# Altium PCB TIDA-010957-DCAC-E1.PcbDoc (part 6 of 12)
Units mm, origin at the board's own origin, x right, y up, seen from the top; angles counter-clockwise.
Board outline 300 x 300 mm, 4 copper layers (Top Layer, Layer 1, Layer 2, Bottom Layer), stack 1.787 mm thick; 1159 components, 619 nets, 3431 pads, 2942 vias.
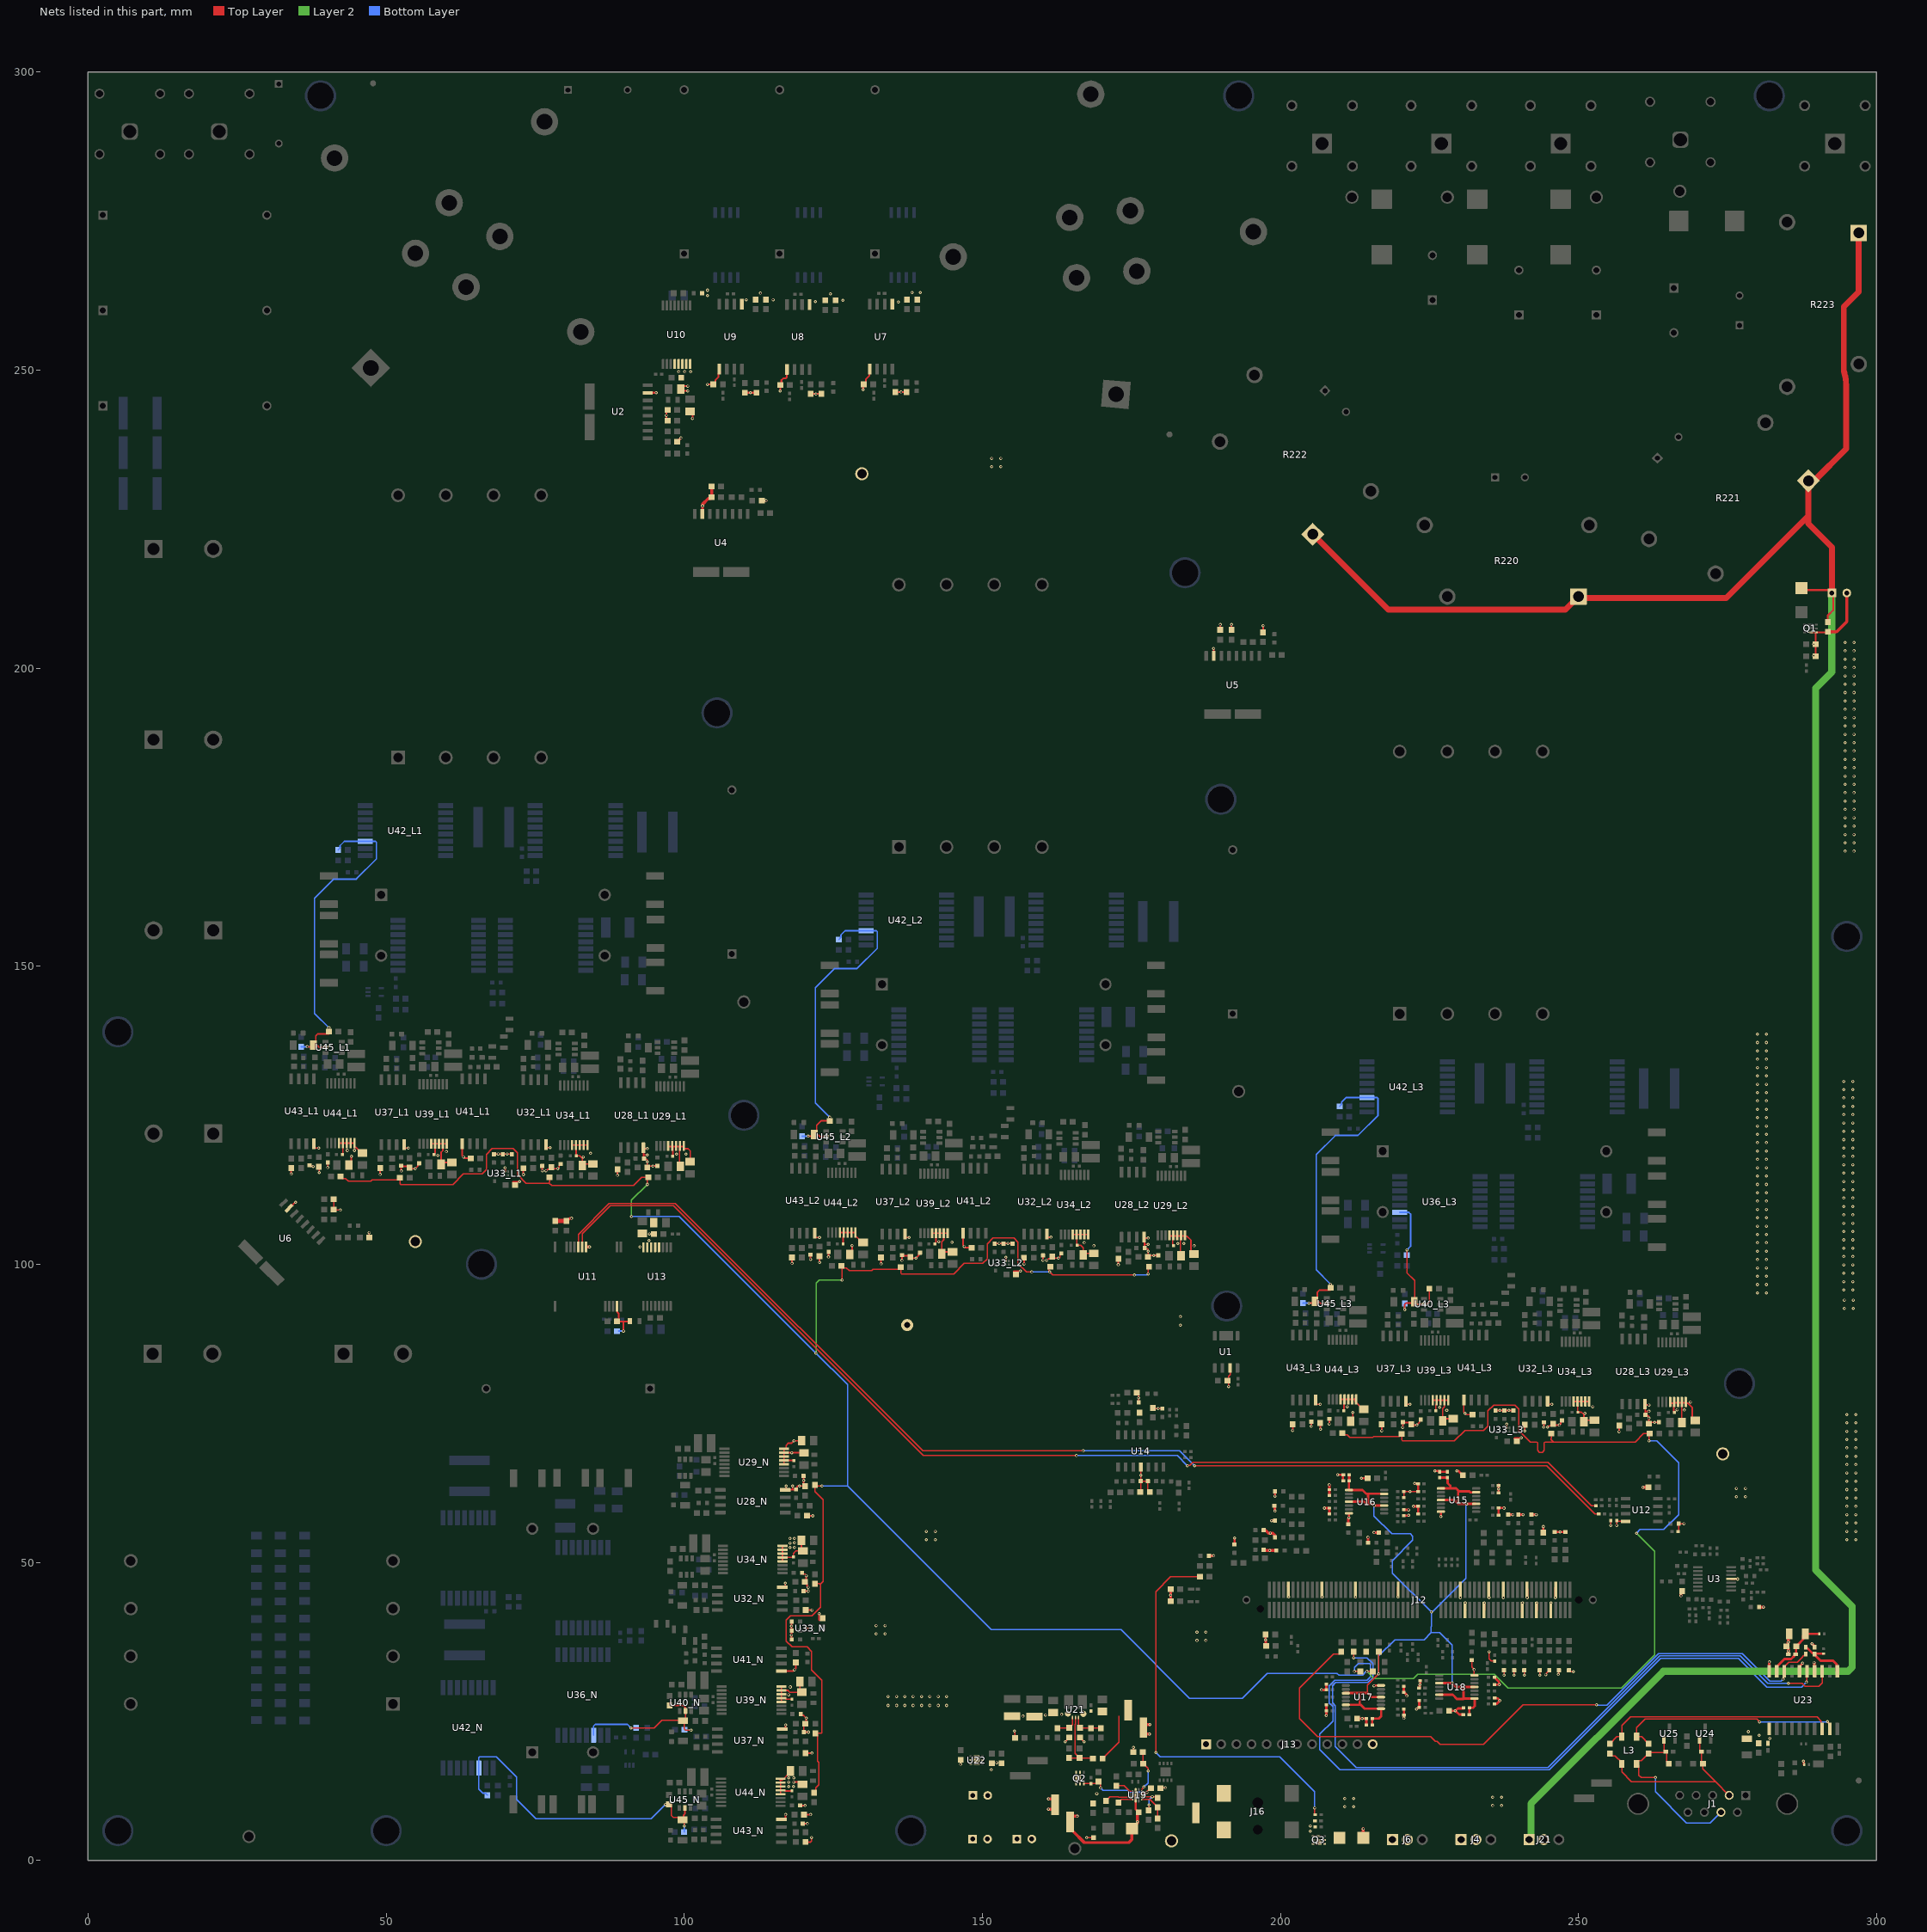
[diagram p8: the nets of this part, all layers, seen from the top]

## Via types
v1: diameter 0.508, hole 0.254, Top Layer to Bottom Layer, tented both sides, 2942 vias

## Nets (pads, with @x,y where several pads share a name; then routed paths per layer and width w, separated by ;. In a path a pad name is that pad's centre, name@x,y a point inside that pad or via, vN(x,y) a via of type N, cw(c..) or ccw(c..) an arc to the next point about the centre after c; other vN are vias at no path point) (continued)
10V_S3_GaN_L3: C229_L3.1 C232_L3.1 R306_L3.2 R310_L3.2 U36_L3.11 U40_L3.5 | length 27.2
  Top Layer w0.254: v1(220.842,92.373) 220.842,93.303 221.047,93.508 C232_L3.1@222.429,93.508 ; v1(221.222,102.422) 221.222,98.546 222.51,97.257 222.51,93.427 222.654,93.283 U40_L3.5@224.083,93.283 224.103,93.303 224.61,93.303 224.983,93.676 R310_L3.2@224.983,95.942
  Bottom Layer w0.254: U36_L3.11@220,108.7 221.544,108.7 221.824,108.42 221.824,103.025 v1(221.222,102.422) C229_L3.1@221.222,101.55 ; v1(220.842,92.373) 220.842,93.378 R306_L3.2@220.897,93.433
10V_S3_GaN_N: C229_N.1 C232_N.1 R306_N.2 R310_N.2 U36_N.11 U40_N.5 | length 27.2
  Top Layer w0.254: v1(91.078,22.222) 94.954,22.222 96.243,23.51 100.073,23.51 100.217,23.654 U40_N.5@100.217,25.083 100.197,25.103 100.197,25.61 99.824,25.983 R310_N.2@97.558,25.983 ; C232_N.1@99.992,23.429 99.992,22.047 100.197,21.842 v1(101.127,21.842)
  Bottom Layer w0.254: U36_N.11@84.8,21 84.8,22.544 85.08,22.824 90.475,22.824 v1(91.078,22.222) C229_N.1@91.95,22.222 ; R306_N.2@100.067,21.897 100.122,21.842 v1(101.127,21.842)
10V_S4_GaN_L1: C247_L1.1 C249_L1.1 R323_L1.2 R327_L1.2 U42_L1.11 U45_L1.5 | length 55.3
  Top Layer w0.254: v1(36.786,136.484) 37.513,136.484 C249_L1.1@37.811,136.783 ; U45_L1.5@39.402,136.383 38.801,136.383 38.551,136.633 37.961,136.633 C249_L1.1@37.811,136.783 ; U45_L1.5@39.479,136.383 U45_L1.5@39.801,136.383 ; v1(40.403,139.667) 40.403,138.659 38.535,138.659 38.21,138.334 38.21,137.181 C249_L1.1@37.811,136.783
  Bottom Layer w0.254: R323_L1.2@35.768,136.509 35.793,136.484 v1(36.786,136.484) ; v1(40.403,139.667) 38,142.07 38,161.388 41.231,164.619 44.245,164.619 45.003,164.619 48.375,167.991 48.375,170.801 48.226,170.95 U42_L1.11@46.5,170.95 43,170.95 42.275,170.225 42.275,169.825 C247_L1.1@41.95,169.5
10V_S4_GaN_L2: C247_L2.1 C249_L2.1 R323_L2.2 R327_L2.2 U42_L2.11 U45_L2.5 | length 55.1
  Top Layer w0.254: v1(120.786,121.484) 121.513,121.484 C249_L2.1@121.811,121.783 ; U45_L2.5@123.402,121.383 122.801,121.383 122.551,121.633 121.961,121.633 C249_L2.1@121.811,121.783 ; U45_L2.5@123.479,121.383 U45_L2.5@123.801,121.384 ; v1(124.403,124.667) R327_L2.2@124.403,124.134 ; C249_L2.1@121.811,121.783 122.21,122.181 122.21,123.334 122.935,124.059 R327_L2.2@124.328,124.059 ; R327_L2.2@124.328,124.059 R327_L2.2@124.403,124.059 R327_L2.2@124.403,124.134 ; R327_L2.2@124.328,124.059 R327_L2.2@124.403,124.134
  Bottom Layer w0.254: R323_L2.2@119.768,121.509 119.793,121.484 v1(120.786,121.484) ; v1(124.403,124.667) 122,127.07 122,146.388 125.231,149.619 128.245,149.619 129.003,149.619 132.375,152.991 132.375,155.801 132.226,155.95 U42_L2.11@130.5,155.95 127,155.95 126.275,155.225 126.275,154.825 C247_L2.1@125.95,154.5
10V_S4_GaN_L3: C247_L3.1 C249_L3.1 R323_L3.2 R327_L3.2 U42_L3.11 U45_L3.5 | length 55.3
  Top Layer w0.254: v1(204.786,93.484) 205.513,93.484 C249_L3.1@205.811,93.783 ; U45_L3.5@207.801,93.384 207.401,93.384 207.402,93.383 206.801,93.383 206.551,93.633 205.961,93.633 C249_L3.1@205.811,93.783 ; v1(208.403,96.667) R327_L3.2@208.403,96.059 208.403,95.659 206.535,95.659 206.21,95.334 206.21,94.181 C249_L3.1@205.811,93.783
  Bottom Layer w0.254: R323_L3.2@203.768,93.509 203.793,93.484 v1(204.786,93.484) ; v1(208.403,96.667) 206,99.07 206,118.388 209.231,121.619 212.245,121.619 213.003,121.619 216.375,124.991 216.375,127.801 216.226,127.95 U42_L3.11@214.5,127.95 211,127.95 210.275,127.225 210.275,126.825 C247_L3.1@209.95,126.5
10V_S4_GaN_N: C247_N.1 C249_N.1 R323_N.2 R327_N.2 U42_N.11 U45_N.5 | length 55.3
  Top Layer w0.254: v1(96.833,9.403) 97.841,9.403 97.841,7.535 98.166,7.21 99.319,7.21 C249_N.1@99.717,6.811 ; v1(100.016,5.786) 100.016,6.513 C249_N.1@99.717,6.811 ; U45_N.5@100.1,8.783 100.1,7.783 99.91,7.594 99.91,7.004 C249_N.1@99.717,6.811
  Bottom Layer w0.254: C247_N.1@67,10.95 66.675,11.275 66.275,11.275 65.55,12 U42_N.11@65.55,15.5 65.55,17.226 65.699,17.375 68.509,17.375 71.881,14.003 71.881,13.245 71.881,10.231 75.112,7 94.43,7 v1(96.833,9.403) ; R323_N.2@99.991,4.768 100.016,4.793 v1(100.016,5.786)
12V: C4.1 C26.1 C27.1 C259.1 C260.1 D3.1 D17.1 J4.1 J6.1 J15.2 J21.1 R220.1 R221.1 R222.1 R223.1 | length 429.7
  Top Layer w0.2: J15.2@161.674,8.6 162.209,9.135 J15.2@162.209,9.358 162.209,9.765 J15.2@161.674,10.3
  Top Layer w0.3: D3.1@287.3,213.1 292,213.1 C26.1@292.5,212.6 ; C27.1@292,207.5 C27.1@291.8,207.7 291.8,208.8 292.7,209.7 C26.1@292.7,212.5
  Top Layer w0.5: v1(161.102,8.611) v1(161.102,8.611) 161.664,8.609 J15.2@161.674,8.6 ; v1(161.113,10.308) 161.115,10.306 161.667,10.306 J15.2@161.674,10.3 ; D17.1@213.9,3.8 v1(213.9,5.286) v1@213.9,5.312
  Top Layer w1: R222.1@205.668,222.2 218.068,209.8 247.8,209.8 R220.1@250,212 ; R220.1@250.214,211.786 274.786,211.786 288.551,225.551 ; C26.1@292.5,212.6 292.5,220.3 288.551,224.249 288.551,225.551 ; R223.1@297,273 297,263.1 294.492,260.592 294.492,249.922 cw(c284.326,247.007) 294.902,247.007 294.902,236.802 289.519,231.419 R221.1@288.551,231.419 288.551,225.551
  Layer 2 w1.2: J21.1@241.7,3.5 242.025,3.825 242.025,9.525 264.218,31.718 295.197,31.718 295.9,32.42 295.9,42.6 289.777,48.723 289.777,48.8 289.777,196.641 292.5,199.364 C26.1@292.5,212.6
12V_FET_DRAIN: Q2.1 Q2.2 Q2.5 Q2.6 Q2.8 R210.1
+5VISO_DC-: C87.2 C88.1 L8.2 U11.5 | length 7.2
  Top Layer w0.3: C88.1@88.729,90.418 89,90.689 89,91.717 88.804,91.913 88.804,92.879 U11.5@88.729,92.954 ; C88.1@88.8,90.4 89.8,90.4 ; v1(89.8,88.8) 89.8,90.4 ; L8.2@90.853,90.4 89.8,90.4
  Bottom Layer w0.3: C87.2@89,88.8 v1(89.8,88.8)
+5VISO_PCC: C54.1 C55.2 C61.1 C62.2 C68.1 C69.2 FB10.1 U7.1 U8.1 U9.1
  other v1: 135.9,261.4 122,261.5 126.6,261.7 110.4,261.8 114.9,261.8 103.9,262.5 124.5,262.8 112.8,262.9 138.2,263 139.6,263 103.9,263.4
+12V_OUT: C133.1 D4.2 D5.1 J15.1 J17.1 R205.2 R209.2 TP5.1 U19.6 | length 28.4
  Top Layer w0.2: J15.1@164.749,6.437 164.749,6.865 J15.1@165.284,7.4 ; v1(167.5,3.8) 167.504,3.796 D4.2@168.682,3.796 ; D5.1@175.1,5.321 D5.1@175.119,5.34 ; v1(175.334,18.976) 175.334,18.18 R205.2@175.339,18.175 ; C133.1@175.841,8.469 C133.1@176.216,8.094 ; J17.1@177.527,22.8 J17.1@177.021,22.294 177.021,21.735 J17.1@177.556,21.2 ; R209.2@179.879,12.125 179.913,12.16 v1(180.72,12.16)
  Top Layer w0.3: U19.6@175.729,10.925 175.729,8.581 C133.1@175.841,8.469
  Top Layer w0.5: J15.1@164.749,6.437 165.134,6.052 165.134,4.964 167.102,2.995 174.595,2.995 175.1,3.5 D5.1@175.1,5.321 ; J15.1@165.284,7.4 v1(165.9,7.4) ; D5.1@175.119,5.34 176.027,6.248 176.027,7.894 C133.1@176.227,8.094 ; J17.1@177.527,22.8 v1(178.1,22.8) ; J17.1@177.556,21.2 v1(178,21.2)
  other v1: 176,6.5 169.2,11.2
AUX_IN_PWR: J14.1 J16.1 J16.1A
BUFF_EN: C108.1 C115.1 C120.1 C126.1 R65.1 R169.2 R184.2 R189.2 R199.2 U15.1 U15.4 U15.10 U15.13 U16.1 U16.4 U16.10 U16.13 U17.1 U17.4 U17.10 U17.13 U18.1 U18.4 U18.10 U18.13 | length 151.5
  Top Layer w0.2: 214.623,28.077 214.623,29.424 216.499,31.3 R65.1@216.5,35
  Top Layer w0.4: U17.10@210.8,28.077 213.3,28.077 ; U17.13@210.966,26.102 213.3,26.102 ; U16.4@211.498,60.175 214.025,60.175 214.4,59.8 214.7,59.8 ; C115.1@211.5,63.6 211.5,62.127 U16.1@211.498,62.125 213.775,62.125 214.4,61.5 214.7,61.5 ; R184.2@211.5,64.7 211.506,64.7 211.548,64.658 C115.1@211.548,63.675 ; 213.3,28.1 213.3,28.077 ; C120.1@215.4,22.7 R189.2@215.4,23.8 216.5,23.8 216.9,24.2 U17.1@216.9,25.4 ; U16.10@216.8,59.55 v1(215.725,59.55) 215.475,59.8 214.7,59.8 ; U17.1@216.866,25.452 214.148,25.452 213.498,26.102 213.3,26.102 ; U17.4@216.866,27.402 215.298,27.402 214.623,28.077 213.3,28.077 ; U16.13@217.3,61.5 214.7,61.5 ; U18.13@226.65,27.8 228.9,27.8 229.6,27.1 230.7,27.1 230.7,29.1 ; U18.10@226.65,29.75 226.658,29.758 228.766,29.758 v1(228.773,29.765) 229.438,29.1 230.7,29.1 ; C108.1@226.7,64.2 R169.2@228,64.2 228.05,64.15 228.05,63.3 228.5,62.85 228.5,62.442 ; U15.4@226.921,60.452 229.148,60.452 229.798,59.802 ; U15.1@226.921,62.402 228.065,62.402 ; 228.105,62.402 229.495,62.402 229.798,62.099 ; 229.798,62.102 229.798,59.802 ; 229.798,62.102 230,61.9 231.697,61.9 231.87,61.727 U15.13@232.2,61.727 ; 230.7,27.15 U18.1@232.55,27.15 ; R199.2@231.7,24.689 C126.1@231.7,25.6 232.3,25.6 232.6,25.9 U18.1@232.6,27.1 ; U18.4@232.6,29.1 U18.4@232.55,29.1 230.7,29.1 ; U15.10@232.698,59.802 229.798,59.802 ; 213.3,26.102 213.3,28.077 ; 214.7,59.8 214.7,61.5
  Bottom Layer w0.2: v1(215.725,59.55) 215.7,59.525 215.7,57.8 218.7,54.8 221.8,54.8 222.2,54.4 222.2,53.7 218.8,50.3 218.8,48.2 v1(225.31,41.69) ; v1(216.5,31.3) 216.5,34.3 219.2,37 224.1,37 225.3,38.2 ; v1(228.773,29.765) 228.773,36.127 226.7,38.2 225.3,38.2 ; v1(231.248,59.802) 231.1,59.654 231.1,47.3 225.628,41.828 225.558,41.828 225.42,41.69 v1(225.31,41.69) ; 225.3,38.2 225.3,39.24 225.31,39.249 v1(225.31,41.69)
CAN_EN: R88.1 R224.1 U23.8 | length 112.6
  Top Layer w0.2: R88.1@210.2,35 210.2,34.975 209.825,34.6 208.907,34.6 203.2,28.893 203.2,23.8 206.2,20.8 225.2,20.8 226,20 226.279,20 226.779,19.5 234.1,19.5 240.7,26.1 v1(253,26.1) ; v1(284.3,30.4) 284.378,30.478 284.378,31.608 U23.8@284.52,31.75 284.52,32.5 285.248,33.228 286.728,33.228 287.6,34.1 287.6,34.15 R224.1@288.1,34.65
  Bottom Layer w0.2: v1(253,26.1) 253.056,26.044 254.744,26.044 263.4,34.7 277.5,34.7 282.1,30.1 284,30.1 v1(284.3,30.4)
CAN_GND2: C153.2 C154.2 C155.2 FB18.1 U23.11 | length 0.8
  Top Layer w0.2: v1(287.725,16.675) v1@287.787,16.612 ; FB18.1@287.787,16.113 FB18.1@287.85,16.05
  Top Layer w0.4: FB18.1@287.787,16.113 v1@287.787,16.612
  Bottom Layer w0.2: v1(287.725,16.675) v1@287.725,16.775
  other v1: 282.1,20.5 280.3,21 278.5,21.6
CAN_RX: R71.1 U23.5 | length 121.2
  Top Layer w0.2: v1(212.4,31.7) R71.1@213.4,31.7 ; v1(288.2,29.9) 288.265,29.965 288.265,31.685 U23.5@288.33,31.75
  Bottom Layer w0.2: v1(212.4,31.7) 212.4,32.4 213.05,33.05 214.908,33.05 215.105,32.853 215.105,30.817 214.51,30.222 209.122,30.222 208.2,29.3 208.2,26.419 208.8,25.819 208.8,23.383 206.6,21.183 206.6,18.6 210,15.2 245.066,15.2 263.766,33.9 276.8,33.9 281.605,29.095 287.395,29.095 v1(288.2,29.9)
CAN_TX: R84.1 U23.3 | length 119.9
  Top Layer w0.2: v1(212.3,34) R84.1@212.3,35 ; v1(285.2,29.7) 287.5,29.7 288,29.2 290.3,29.2 290.87,29.77 U23.3@290.87,31.75
  Bottom Layer w0.2: v1(212.3,34) 214.524,34 215.505,33.019 215.505,30.651 214.675,29.822 209.288,29.822 208.733,29.267 208.733,26.451 209.2,25.984 209.2,19.099 212.699,15.6 244.9,15.6 263.6,34.3 277.1,34.3 281.7,29.7 v1(285.2,29.7)
CAN_VDD: C6.1 C147.1 C148.1 FB12.2 U23.9 | length 11.2
  Top Layer w0.2: C148.1@286.4,34.6 C148.1@286.5,34.7
  Top Layer w0.4: U23.9@283.25,31.75 283.25,32.5 284.55,33.8 285.666,33.8 286.2,34.334 286.2,34.5 C148.1@286.267,34.567 ; C148.1@286.5,34.7 C147.1@286.5,35.9 286.525,35.9 286.8,36.175 286.8,36.2 287.7,37.1 287.7,37.666 288.05,38.016 FB12.2@290.4,38.016
CAN_VIO: C152.1 FB13.2 R224.2 U23.1 | length 9.2
  Top Layer w0.2: C152.1@289.6,34.5 C152.1@289.6,34.6
  Top Layer w0.4: R224.2@288.1,35.734 288.266,35.734 289.2,34.8 289.5,34.8 289.6,34.7 C152.1@289.6,34.6 289.7,34.7 FB13.2@291.1,34.7 ; C152.1@289.6,34.5 290.6,33.5 292.7,33.5 293.31,32.89 293.31,31.85 U23.1@293.41,31.75
CANH: L3.1 R225.2 U23.19 | length 38.2
  Top Layer w0.2: R225.2@261.75,19.55 261.75,19.575 260.575,20.75 L3.1@259.75,20.75 259.75,22.25 261.2,23.7 279.899,23.7 280.347,23.252 v1(280.377,23.252) ; v1(291.746,23.3) 291.805,23.241 291.805,23.135 292.14,22.8 U23.19@292.14,22.05
  Bottom Layer w0.2: v1(280.377,23.252) 291.698,23.252 v1(291.746,23.3)
CANHI: C156.1 J1.7 L3.4 R225.1 R226.2 U25.1 | length 31.4
  Top Layer w0.2: v1(262.9,13.9) 260.5,13.9 260.1,14.3 260.1,15.85 L3.4@259.75,16.2 259.75,16.375 260.1,16.725 260.526,16.725 261.35,17.55 261.375,17.55 261.75,17.925 R225.1@261.75,17.95 261.9,18.1 264.4,18.1 C156.1@264.55,18.25 ; U25.1@264.3,20.2 264.37,20.13 264.37,18.43 C156.1@264.55,18.25 ; R226.2@265.15,16.25 264.808,16.592 264.808,18.092 C156.1@264.65,18.25 C156.1@264.55,18.25
  Bottom Layer w0.2: v1(262.9,13.9) 262.9,11.528 268.128,6.3 272.105,6.3 J1.7@273.885,8.08
CANL: L3.2 R228.2 U23.18 | length 40.2
  Top Layer w0.2: R228.2@255.25,19.55 255.25,19.575 256.425,20.75 L3.2@257.25,20.75 257.25,22.65 258.7,24.1 290,24.1 290.7,23.4 290.7,22.22 U23.18@290.87,22.05
CANLO: C158.2 J1.2 L3.3 R227.1 R228.1 U24.1 | length 32
  Top Layer w0.2: R228.1@255.25,17.95 255.25,17.925 255.625,17.55 256.125,17.55 257.25,16.425 L3.3@257.25,16.2 257.25,14.85 258.9,13.2 272.99,13.2 ; U24.1@270.3,20.2 270.369,20.131 270.369,18.45 270.569,18.25 C158.2@270.65,18.25 270.65,16.45 R227.1@270.85,16.25 270.85,15.34 272.99,13.2 ; J1.2@275.27,10.92 272.99,13.2
DC_VSEN+: R139.2 U11.11 | length 197
  Top Layer w0.2: U11.11@82.229,102.904 82.229,105.029 87.4,110.2 98.515,110.2 140.015,68.7 v1(166.9,68.7) ; v1(185.6,66.2) 244.681,66.2 252.4,58.481 252.741,58.14 R139.2@253.383,58.14
  Bottom Layer w0.2: v1(166.9,68.7) 183.1,68.7 v1(185.6,66.2)
DC_VSEN-: R141.2 U11.10 | length 195.5
  Top Layer w0.2: U11.10@82.879,102.904 82.879,105.114 87.566,109.8 98.2,109.8 140.1,67.9 v1(165.8,67.9) ; v1(184.4,66.2) 184.478,66.278 184.823,66.278 185.349,66.805 244.895,66.805 252.2,59.5 R141.2@252.85,59.5
  Bottom Layer w0.2: v1(165.8,67.9) 182.7,67.9 v1(184.4,66.2)
DCDC_EN: C146.1 R213.1 R216.1 U21.6 | length 11.3
  Top Layer w0.2: R216.1@164.538,17.171 C146.1@166.32,17.171 ; U21.6@165.633,24.004 165.633,22.874 165.545,22.786 165.545,17.971 166.32,17.196 C146.1@166.32,17.171 ; R213.1@168.571,17.096 168.496,17.171 C146.1@166.32,17.171
DCDC_FB: C137.2 R214.1 R215.2 U21.7 | length 5.4
  Top Layer w0.2: U21.7@166.133,24.004 166.133,22.475 R215.2@166.383,22.225 168.177,22.225 C137.2@168.207,22.196 R214.1@169.858,22.196
DCDC_PG: R218.1 R219.2 U21.5 | length 4
  Top Layer w0.2: R218.1@162.608,22.196 164.554,22.196 R219.2@164.583,22.225 164.583,22.25 165.133,22.8 U21.5@165.133,24.004
DCDC_VIN: C141.1 C142.2 J17.2 R213.2 U21.1 | length 8.2
  Top Layer w0.2: R213.2@170.171,17.096 170.196,17.096 170.571,17.471 170.571,17.496 172.9,19.825 172.9,24.2
EF_dVdt: C135.1 U19.7 | length 2.8
  Top Layer w0.2: C135.1@172.479,12.525 173.775,12.525 174.708,11.592 174.912,11.592 174.929,11.575
EF_EN: R204.1 R208.2 U19.1 | length 5.1
  Top Layer w0.2: U19.1@176.729,10.225 178.116,10.225 179.391,8.95 R208.2@179.391,8.925 R204.1@179.391,7.046
EF_ILIM: R206.2 U19.9 | length 4.7
  Top Layer w0.2: R206.2@170.729,9.975 170.729,10 171.386,10.658 172.85,10.658 172.874,10.634 174.338,10.634 174.404,10.7 U19.9@175.079,10.7
EF_ITIMER: C134.1 U19.10 | length 2.6
  Top Layer w0.2: C134.1@172.851,9.7 172.851,9.725 173.351,10.225 U19.10@175.229,10.225
EF_OVLO: R208.1 R211.2 U19.2 | length 5.1
  Top Layer w0.2: U19.2@176.879,10.7 179.216,10.7 R208.1@179.391,10.525 ; R211.2@177.9,8.4 177.965,8.465 v1(177.965,9.298)
  Bottom Layer w0.2: v1(177.965,9.298) 177.965,10.165 v1(178.5,10.7)
EF_PG: C136.1 Q2.3 R209.1 R212.2 U19.3 | length 13.8
  Top Layer w0.2: Q2.3@167.032,12.834 167.082,12.884 169.115,12.884 R212.2@169.482,13.25 169.831,12.901 v1(169.831,12.16) ; U19.3@176.879,11.15 176.904,11.175 177.294,11.175 177.539,11.42 v1(177.622,11.42) ; v1@177.555,11.434 177.563,11.434 178.254,12.125 R209.1@178.279,12.125
  Bottom Layer w0.2: v1(169.831,12.16) 170.249,11.742 174.338,11.742 174.614,11.466 177.576,11.466 v1(177.622,11.42)
EF_PGTH: R205.1 R207.2 U19.4 | length 7.1
  Top Layer w0.2: 176.7,11.9 v1(177.1,12.3) ; R205.1@176.939,18.175 176.939,16.29 R207.2@176.979,16.25 177.004,16.25 177.379,15.875 177.379,15.85 177.8,15.429 v1(177.8,15)
  Bottom Layer w0.2: v1(177.1,12.3) 177.8,13 v1(177.8,15)
EN_AUX_ISO_DCAC: R67.1 R287_L1.2 R287_L2.2 R287_L3.2 R287_N.2 R298_L1.2 R298_L2.2 R298_L3.2 R298_N.2 R308_L1.2 R308_L2.2 R308_L3.2 R308_N.2 R325_L1.2 R325_L2.2 R325_L3.2 R325_N.2 | length 558
  Top Layer w0.2: R325_L1.2@42.369,114.709 42.678,114.4 43.2,114.4 43.673,113.927 47.427,113.927 47.642,114.142 51.955,114.142 R308_L1.2@52.33,114.517 52.33,113.517 52.447,113.4 61.195,113.4 62.931,115.136 66.079,115.136 66.811,115.868 66.811,118.411 67.8,119.4 71.3,119.4 72,118.7 72,115.1 73.483,113.617 77.383,113.617 ; R298_L1.2@77.425,114.583 77.425,113.825 77.383,113.783 77.383,113.617 ; v1(93.8,113.4) 93.8,114.42 R287_L1.2@93.963,114.583 92.883,114.583 91.5,113.2 77.8,113.2 77.383,113.617 ; R325_N.2@121.791,11.369 122.1,11.678 122.1,12.2 122.573,12.673 122.573,16.427 122.358,16.642 122.358,20.955 R308_N.2@121.983,21.33 122.983,21.33 123.1,21.447 123.1,30.195 121.364,31.931 121.364,35.079 120.632,35.811 118.089,35.811 117.1,36.8 117.1,40.3 117.8,41 121.4,41 122.883,42.483 122.883,46.383 ; R298_N.2@121.917,46.425 122.675,46.425 122.717,46.383 122.883,46.383 ; v1(123.1,62.8) 122.08,62.8 R287_N.2@121.917,62.963 121.917,61.883 123.3,60.5 123.3,46.8 122.883,46.383 ; v1(126.49,97.36) 126.49,99.334 126.556,99.4 127.2,99.4 127.673,98.927 131.427,98.927 131.642,99.142 135.955,99.142 R308_L2.2@136.33,99.517 136.33,98.517 136.447,98.4 145.195,98.4 146.931,100.136 150.079,100.136 150.811,100.868 150.811,103.411 151.8,104.4 155.3,104.4 156,103.7 156,100.1 157.4,98.7 v1(158.3,98.7) ; R298_L2.2@161.425,99.583 161.155,99.313 161.155,98.845 161.8,98.2 v1(175.5,98.2) ; v1(177.8,98.4) 177.8,99.42 R287_L2.2@177.963,99.583 ; R325_L3.2@210.369,71.709 210.678,71.4 211.2,71.4 211.673,70.927 215.427,70.927 215.642,71.142 219.955,71.142 R308_L3.2@220.33,71.517 220.33,70.517 220.447,70.4 229.195,70.4 230.931,72.136 234.079,72.136 234.811,72.868 234.811,75.411 235.8,76.4 239.3,76.4 240,75.7 240,72.1 241.9,70.2 243.013,70.2 243.13,70.083 243.13,68.787 243.471,68.446 243.929,68.446 244.254,68.771 244.254,70.083 244.371,70.2 245.8,70.2 ; v1(214.5,31.7) R67.1@215.5,31.7 ; R298_L3.2@245.425,71.583 245.425,70.825 245.383,70.783 245.383,70.617 245.8,70.2 ; v1(261.8,70.4) 261.8,71.42 R287_L3.2@261.963,71.583 260.883,71.583 259.5,70.2 245.8,70.2
  Layer 2 w0.2: v1(91.161,108.043) 91.161,110.761 v1(93.8,113.4) ; v1(122.106,85.106) 122.123,85.123 122.123,96.849 122.635,97.36 v1(126.49,97.36) ; v1(214.5,31.7) 215.7,30.5 222.3,30.5 223,31.2 235.9,31.2 238.2,28.9 257.2,28.9 262.8,34.5 262.8,51.822 v1(259.732,54.891)
  Bottom Layer w0.2: v1(91.161,108.043) 99.157,108.043 122.094,85.106 v1(122.106,85.106) ; v1@122.1,85.1 127.4,79.8 127.4,62.8 ; v1(123.1,62.8) 127.4,62.8 ; v1(158.3,98.7) v1(161.3,98.7) ; v1(175.5,98.2) 177.517,98.2 177.717,98.4 v1(177.8,98.4) ; v1(214.5,31.7) 214.408,31.7 213.803,31.095 209.805,31.095 209.495,31.405 197.805,31.405 193.6,27.2 184.766,27.2 173.266,38.7 151.5,38.7 127.4,62.8 ; v1(259.732,54.891) 260.341,55.5 264.3,55.5 266.8,58 266.8,66.7 263.1,70.4 v1(261.8,70.4)
EN_BUFF_PWM_DCDC: R69.1
FAN_CTRL: R329.1 R334.2 | length 68.7
  Top Layer w0.2: v1(179.1,18.1) 179.1,45.1 181.6,47.6 R334.2@186.5,47.6 ; v1(205.752,8.822) 205.752,7.779 R329.1@205.85,7.681
  Bottom Layer w0.2: v1(179.1,18.1) 179.8,17.4 199.9,17.4 205.752,11.548 v1(205.752,8.822)
FAN_SN: D17.2 J4.2 J6.2 J21.2 Q3.1 Q3.2 Q3.5 Q3.6 Q3.8
GND: C4.2 C5.2 C6.2 C13.2 C14.2 C15.1 C16.2 C26.2 C27.2 C28.2 C30.2 C31.1 C33.2 C34.2 C36.2 C37.1 C39.2 C40.2 C42.2 C43.1 C45.2 C46.2 C47.1 C49.2 C50.1 C52.2 C53.2 C56.1 C57.2 C59.1 C60.2 C63.1 C64.2 C66.1 C67.2 C70.1 C71.2 C73.1 C74.2 C77.2 C78.2 C79.2 C80.1 C81.2 C82.2 C83.1 C84.2 C91.2 C92.2 C93.2 C95.1 C96.2 C98.1 C99.2 C101.1 C102.2 C104.1 C105.2 C107.2 C108.2 C109.2 C110.2 C111.2 C112.2 C113.2 C114.2 C115.2 C116.2 C117.2 C118.2 C119.2 C120.2 C121.2 C122.2 C123.2 C124.2 C125.2 C126.2 C127.2 C128.2 C129.2 C130.2 C138.2 C139.2 C140.2 C143.2 C144.2 C145.2 C147.2 C148.2 C152.2 C159.1 C160.1 C161.1 C162.1 C186_L1.2 C186_L2.2 C186_L3.2 C186_N.2 C191_L1.1 C191_L2.1 C191_L3.1 C191_N.1 C196_L1.1 C196_L2.1 C196_L3.1 C196_N.1 C197_L1.2 C197_L2.2 C197_L3.2 C197_N.2 C198_L1.2 C198_L2.2 C198_L3.2 C198_N.2 C199_L1.1 C199_L2.1 C199_L3.1 C199_N.1 C200_L1.2 C200_L2.2 C200_L3.2 C200_N.2 C205_L1.1 C205_L2.1 C205_L3.1 C205_N.1 C206_L1.1 C206_L2.1 C206_L3.1 C206_N.1 C207_L1.1 C207_L2.1 C207_L3.1 C207_N.1 C209_L1.1 C209_L2.1 C209_L3.1 C209_N.1 C219_L1.1 C219_L2.1 C219_L3.1 C219_N.1 C220_L1.2 C220_L2.2 C220_L3.2 C220_N.2 C221_L1.2 C221_L2.2 C221_L3.2 C221_N.2 C222_L1.1 C222_L2.1 C222_L3.1 C222_N.1 C223_L1.2 C223_L2.2 C223_L3.2 C223_N.2 C224_L1.2 C224_L2.2 C224_L3.2 C224_N.2 C230_L1.1 C230_L2.1 C230_L3.1 C230_N.1 C231_L1.1 C231_L2.1 C231_L3.1 C231_N.1 C236_L1.1 C236_L2.1 C236_L3.1 C236_N.1 C237_L1.2 C237_L2.2 C237_L3.2 C237_N.2 C238_L1.2 C238_L2.2 C238_L3.2 C238_N.2 C239_L1.1 C239_L2.1 C239_L3.1 C239_N.1 C240_L1.2 C240_L2.2 C240_L3.2 C240_N.2 C243_L1.2 C243_L2.2 C243_L3.2 C243_N.2 C248_L1.1 C248_L2.1 C248_L3.1 C248_N.1 C253_L1.1 C253_L2.1 C253_L3.1 C253_N.1 C254_L1.2 C254_L2.2 C254_L3.2 C254_N.2 C255_L1.2 C255_L2.2 C255_L3.2 C255_N.2 C256_L1.1 C256_L2.1 C256_L3.1 C256_N.1 C259.2 C260.2 C261.2 C262.2 C263.1 J12.7 J12.10 J12.16 J12.19 J12.22 J12.29 J12.35 J12.38 J12.46 J12.47 J12.65 J12.83 J12.97 J12.111 J13.1 J13.12 Q1.4 Q1.7 Q3.4 Q3.7 R23.2 R81.1 R82.1 R97.1 R105.1 R113.1 R121.1 R129.1 R137.2 R144.2 R149.2 R154.2 R159.2 R169.1 R170.1 R171.1 R172.1 R173.1 R184.1 R185.1 R186.1 R187.1 R188.1 R189.1 R190.1 R191.1 R192.1 R193.1 R199.1 R200.1 R201.1 R202.1 R203.1 R215.1 R217.1 R219.1 R284_L1.1 R284_L2.1 R284_L3.1 R284_N.1 R295_L1.1 R295_L2.1 R295_L3.1 R295_N.1 R305_L1.1 R305_L2.1 R305_L3.1 R305_N.1 R322_L1.1 R322_L2.1 R322_L3.1 R322_N.1 R330.1 R333.2 TP1.1 TP11.1 TP12.1 TP13.1 U1.3 U2.9 U3.11 U4.9 U5.9 U6.9 U7.5 U8.5 U9.5 U10.4 U10.5 U10.6 U10.7 U10.8 U11.9 U12.4 U13.4 U13.5 U13.6 U13.7 U13.8 U14.11 U15.7 U16.7 U17.7 U18.7 U21.4 U22.2 U22.3 U22.5 U22.7@149.05,16.826 U23.4 U23.6 U23.10 U28_L1.4 U28_L2.4 U28_L3.4 U28_N.4 U29_L1.4 U29_L1.5 U29_L1.6 U29_L1.7 U29_L1.8 U29_L2.4 U29_L2.5 U29_L2.6 U29_L2.7 U29_L2.8 U29_L3.4 U29_L3.5 U29_L3.6 U29_L3.7 U29_L3.8 U29_N.4 U29_N.5 U29_N.6 U29_N.7 U29_N.8 U32_L1.4 U32_L2.4 U32_L3.4 U32_N.4 U33_L1.2 U33_L2.2 U33_L3.2 U33_N.2 U34_L1.4 U34_L1.5 U34_L1.6 U34_L1.7 U34_L1.8 U34_L2.4 U34_L2.5 U34_L2.6 U34_L2.7 U34_L2.8 U34_L3.4 U34_L3.5 U34_L3.6 U34_L3.7 U34_L3.8 U34_N.4 U34_N.5 U34_N.6 U34_N.7 U34_N.8 U37_L1.4 U37_L2.4 U37_L3.4 U37_N.4 U39_L1.4 U39_L1.5 U39_L1.6 U39_L1.7 U39_L1.8 U39_L2.4 U39_L2.5 U39_L2.6 U39_L2.7 U39_L2.8 U39_L3.4 U39_L3.5 U39_L3.6 U39_L3.7 U39_L3.8 U39_N.4 U39_N.5 U39_N.6 U39_N.7 U39_N.8 U41_L1.5 U41_L2.5 U41_L3.5 U41_N.5 U43_L1.4 U43_L2.4 U43_L3.4 U43_N.4 U44_L1.4 U44_L1.5 U44_L1.6 U44_L1.7 U44_L1.8 U44_L2.4 U44_L2.5 U44_L2.6 U44_L2.7 U44_L2.8 U44_L3.4 U44_L3.5 U44_L3.6 U44_L3.7 U44_L3.8 U44_N.4 U44_N.5 U44_N.6 U44_N.7 U44_N.8 | length 479.5
  Top Layer w0.2: U6.9@33.702,109.399 33.75,109.399 34.752,110.4 v1(34.8,110.4) ; C53.2@41.225,110.9 R129.1@41.225,109.2 41.337,109.088 v1(42.288,109.088) ; v1(47.172,105.313) 47.172,104.528 C49.2@47.2,104.5 ; C36.2@113,228.1 C36.2@113.026,228.074 ; v1(155.4,21.7) 155.483,21.617 R217.1@155.483,20.55 ; v1@163.858,19.875 v1(163.89,19.907) 164.583,20.6 R219.1@164.583,20.625 ; R215.1@166.383,20.625 166.383,20.6 167.074,19.909 v1(167.074,19.901) ; R149.2@175.891,78.475 176.2,78.166 v1(176.2,77.6) 176.2,76.861 C98.1@176.232,76.829 ; R154.2@176.473,61.784 176.576,61.886 C101.1@176.576,63.625 ; U14.11@176.586,65.984 176.593,65.977 176.593,64.607 v1(176.6,64.6) 176.6,63.649 C101.1@176.576,63.625 ; R159.2@178.1,61.8 177.757,62.143 C104.1@177.757,63.625 C101.1@176.576,63.625 ; R144.2@178.6,75.9 178.7,75.8 v1(179.5,75.8) C95.1@180.2,75.8 ; v1(191.3,79.5) 191.3,80.3 C13.2@191.1,80.5 191.3,80.7 191.3,81.2 191.6,81.5 191.6,82.535 U1.3@191.535,82.6 ; R188.1@220.7,60.85 C119.2@220.7,61.85 220.725,61.875 v1(221.746,61.875) 223.075,61.875 C109.2@223.1,61.9 ; C14.2@232.1,33.6 232.1,32.455 232.5,32.055 v1(232.5,32) 232.5,31.1 U18.7@232.55,31.05 ; v1(235,35) 235.006,34.994 235.006,33.794 235.35,33.45 C263.1@235.925,33.45 ; v1(237.5,31.1) C84.2@237.5,31.9 ; v1(239.2,31.1) C73.1@239.2,31.9 ; v1(240.9,31.1) C37.1@240.9,31.9 ; v1(243.5,31.1) C59.1@243.5,31.9 ; v1(244.5,31.183) 244.559,31.242 244.559,31.359 C102.2@245.1,31.9 ; v1(246.6,31.2) 246.7,31.3 C105.2@246.7,31.9 ; C99.2@248.4,31.9 248.65,31.65 v1(249.125,31.65) ; v1(255.4,56.2) C83.1@255.4,57 ; v1(256.4,56.2) R137.2@256.4,57 256.53,56.87 U12.4@257.9,56.87 ; R333.2@266.7,55.2 266.75,55.2 266.8,55.25 C262.2@266.8,56.5 v1(267.7,56.5) ; U23.10@281.98,31.75 U23.10@281.99,31.76 ; v1@281.99,33.29 v1(282,33.3) ; C147.2@284.786,36.014 C147.2@284.9,35.9 C147.2@285.2,35.6 ; U23.6@287.06,31.75 U23.6@287.06,32.5 ; v1@287.6,33.04 v1(287.6,33.1) ; v1(289.5,33.2) v1@289.55,33.15 ; U23.4@289.55,31.8 U23.4@289.6,31.75 ; C152.2@289.6,35.8 C152.2@289.6,35.9
  Top Layer w0.254: C243_L1.2@34.073,116.155 34.075,116.153 v1(34.075,115.142) ; C248_L1.1@37.175,116.609 37.369,116.415 37.369,116.441 37.398,116.471 37.707,116.471 v1(37.755,116.422) ; U43_L1.4@37.883,120.226 37.883,119.675 38.056,119.502 38.683,119.502 v1(38.685,119.5) ; R322_L1.1@38.685,116.38 38.78,116.285 v1(38.78,115.398) ; v1(40.201,116.23) 40.215,116.244 40.215,117.041 C253_L1.1@40.228,117.055 ; U44_L1.4@42.104,120.338 U44_L1.5@42.754,120.338 ; C256_L1.1@42.653,118.432 42.754,118.532 U44_L1.5@42.754,120.338 ; C255_L1.2@43.77,116.659 44.155,117.044 v1(44.155,118.14) ; C254_L1.2@46,118.671 45.835,118.671 44.891,119.615 44.782,119.615 44.704,119.693 U44_L1.8@44.704,120.338 U44_L1.7@44.054,120.338 U44_L1.6@43.404,120.338 U44_L1.5@42.754,120.338 ; v1(49,115.064) C224_L1.2@49,116.155 ; v1(52.528,115.642) C231_L1.1@52.528,116.184 ; C231_L1.1@52.528,116.434 53.679,116.434 R305_L1.1@53.929,116.184 54.08,116.033 v1(54.879,116.033) 55.328,116.482 55.328,116.742 C236_L1.1@55.541,116.955 ; U37_L1.4@53.034,120.05 53.034,119.673 53.207,119.5 v1(53.733,119.5) ; U39_L1.4@57.56,120.208 U39_L1.5@58.21,120.208 ; C239_L1.1@58.06,118.432 58.183,118.555 58.183,118.676 58.21,118.703 U39_L1.5@58.21,120.208 ; U39_L1.8@60.16,120.208 U39_L1.7@59.51,120.208 ; C237_L1.2@61,117.096 59.355,117.096 59.214,116.955 59.214,118.791 59.51,119.087 U39_L1.7@59.51,120.208 ; U41_L1.5@62.764,120.208 62.764,118.216 v1(62.979,118.001) 63.194,117.786 C240_L1.2@64.2,117.786 ; C206_L1.1@68.075,118.463 68.096,118.484 68.796,118.484 v1(68.817,118.505) 68.838,118.484 69.545,118.484 C209_L1.1@69.566,118.463 69.587,118.484 70.282,118.484 v1(70.303,118.505) 70.324,118.484 71.063,118.484 C207_L1.1@71.084,118.463 ; U33_L1.2@69.956,115.567 v1(69.956,116.18) ; 71.231,113.792 71.323,113.884 v1(72.381,113.884) ; v1(73.005,115.058) C200_L1.2@73.005,116.108 ; v1(76.18,115.698) C205_L1.1@76.18,116.48 ; v1(76.815,115.702) 76.877,115.702 77.091,115.917 77.403,115.917 R295_L1.1@77.75,116.263 77.98,116.033 v1(78.775,116.033) 78.844,116.033 79.027,116.216 79.027,116.507 C219_L1.1@79.25,116.73 ; U32_L1.4@76.815,120.05 76.815,119.723 76.988,119.55 v1(77.503,119.55) ; U34_L1.4@81.175,120 U34_L1.5@81.825,120 ; U34_L1.8@83.775,120 U34_L1.7@83.125,120 U34_L1.6@82.475,120 U34_L1.5@81.825,120 ; C220_L1.2@84.675,116.833 83.063,116.833 82.916,116.98 82.916,117.774 82.508,118.182 C222_L1.1@81.894,118.182 81.859,118.216 81.859,119.966 U34_L1.5@81.825,120 ; v1(88.803,114.934) 88.803,115.908 C186_L1.2@88.825,115.93 ; v1(93.8,118.338) 93.197,118.338 ; v1(93.8,119.401) 93.304,119.401 93.197,119.508 93.197,118.338 ; C196_L1.1@95.497,116.505 95.485,116.492 94.776,116.492 v1(94.763,116.48) 94.025,116.48 R284_L1.1@93.8,116.255 v1(93.8,117.178) 93.8,117.464 93.651,117.613 93.363,117.613 C191_L1.1@93.238,117.738 93.197,117.78 93.197,118.338 ; U29_L1.4@97.447,119.75 U29_L1.5@98.097,119.75 ; C199_L1.1@98.088,118.13 98.093,118.134 98.093,119.745 U29_L1.5@98.097,119.75 ; U29_L1.7@99.222,119.85 U29_L1.7@99.222,119.75 ; C198_L1.2@99.354,116.43 99.222,116.562 U29_L1.7@99.222,119.75 ; C197_L1.2@101,117.204 101,119.021 100.62,119.401 99.872,119.401 99.872,119.672 99.794,119.75 U29_L1.7@99.222,119.75 ; 116,13.497 116.162,13.497 ; U44_N.4@116.162,11.104 U44_N.5@116.162,11.754 ; U43_N.4@116.274,6.883 116.825,6.883 116.998,7.056 116.998,7.683 v1(117,7.685) ; U39_N.4@116.292,26.56 U39_N.5@116.292,27.21 ; U39_N.8@116.292,29.16 U39_N.7@116.292,28.51 ; U41_N.5@116.292,31.764 118.284,31.764 v1(118.499,31.979) 118.714,32.194 C240_N.2@118.714,33.2 ; U37_N.4@116.45,22.034 116.827,22.034 117,22.207 v1(117,22.733) ; U32_N.4@116.45,45.815 116.777,45.815 116.95,45.988 v1(116.95,46.503) ; U34_N.4@116.5,50.175 U34_N.5@116.5,50.825 ; U34_N.8@116.5,52.775 U34_N.7@116.5,52.125 U34_N.6@116.5,51.475 U34_N.5@116.5,50.825 ; U29_N.4@116.75,66.447 U29_N.5@116.75,67.097 ; v1(117.099,62.8) 117.099,62.304 116.992,62.197 118.162,62.197 ; C254_N.2@117.829,15 117.829,14.835 116.491,13.497 116.162,13.497 ; C206_N.1@118.037,37.075 118.016,37.096 118.016,37.796 v1(117.995,37.817) 118.016,37.838 118.016,38.545 C209_N.1@118.037,38.566 118.016,38.587 118.016,39.282 v1(117.995,39.303) 118.016,39.324 118.016,40.063 C207_N.1@118.037,40.084 ; C256_N.1@118.068,11.653 116.908,11.653 116.807,11.754 U44_N.5@116.162,11.754 ; C239_N.1@118.068,27.06 117.087,27.06 116.937,27.21 U39_N.5@116.292,27.21 ; C243_L2.2@118.073,101.155 118.075,101.153 v1(118.075,100.142) ; v1(118.162,62.8) 118.162,62.197 ; v1(118.36,13.155) 119.456,13.155 C255_N.2@119.841,12.77 ; C199_N.1@118.37,67.088 118.366,67.093 116.755,67.093 U29_N.5@116.75,67.097 ; C237_N.2@119.404,30 119.404,28.355 119.545,28.214 117.709,28.214 117.413,28.51 U39_N.7@116.292,28.51 ; C253_N.1@119.445,9.228 119.459,9.215 120.256,9.215 v1(120.27,9.201) ; C236_N.1@119.545,24.541 119.758,24.328 120.018,24.328 v1(120.467,23.879) 120.467,23.08 R305_N.1@120.316,22.929 120.066,22.679 C231_N.1@120.066,21.528 ; C220_N.2@119.667,53.675 119.667,52.063 119.52,51.916 118.726,51.916 118.318,51.508 C222_N.1@118.318,50.894 118.284,50.859 116.534,50.859 U34_N.5@116.5,50.825 ; C197_N.2@119.684,70.4 v1(118.427,70.4) 118.027,70 117.479,70 117.099,69.62 117.099,69.125 117.021,69.047 U29_N.8@116.75,69.047 U29_N.7@116.75,68.397 ; C219_N.1@119.77,48.25 119.993,48.027 120.284,48.027 120.467,47.844 v1(120.467,47.775) 120.467,46.98 R295_N.1@120.237,46.75 120.583,46.403 120.583,46.091 120.798,45.877 v1(120.798,45.815) ; C198_N.2@119.77,68.354 119.727,68.397 v1(118.039,68.397) U29_N.7@116.75,68.397 ; C248_N.1@119.891,6.175 v1(120.658,6.175) ; C196_N.1@119.995,64.497 120.008,64.485 120.008,63.776 v1(120.02,63.763) 120.02,63.025 R284_N.1@120.245,62.8 v1(119.322,62.8) 119.036,62.8 118.887,62.651 118.887,62.363 C191_N.1@118.762,62.238 118.72,62.197 118.162,62.197 ; C205_N.1@120.02,45.18 v1(120.802,45.18) ; R322_N.1@120.12,7.685 120.135,7.7 v1(121.183,7.7) ; C231_N.1@120.316,21.528 v1(120.858,21.528) ; v1(120.32,38.956) U33_N.2@120.933,38.956 ; C243_N.2@120.345,3.073 120.347,3.075 121.209,3.075 121.358,3.224 v1(121.358,3.855) ; C224_N.2@120.345,18 v1(121.436,18) ; C200_N.2@120.392,42.005 v1(121.442,42.005) ; C186_N.2@120.57,57.825 120.592,57.803 v1(121.566,57.803) ; v1(121.175,100.842) C248_L2.1@121.175,101.609 ; U43_L2.4@121.883,105.226 121.883,104.675 122.056,104.502 122.683,104.502 v1(122.685,104.5) ; v1(122.616,41.381) 122.616,40.323 122.708,40.231 ; R322_L2.1@122.685,101.38 122.7,101.365 v1(122.7,100.317) ; v1(124.201,101.23) 124.215,101.244 124.215,102.041 C253_L2.1@124.228,102.055 ; U44_L2.4@126.104,105.338 U44_L2.5@126.754,105.338 ; C256_L2.1@126.653,103.432 126.653,104.592 126.754,104.693 U44_L2.5@126.754,105.338 ; C255_L2.2@127.77,101.659 128.155,102.044 v1(128.155,103.14) ; C254_L2.2@130,103.671 129.835,103.671 128.891,104.615 128.782,104.615 128.704,104.693 U44_L2.8@128.704,105.338 U44_L2.7@128.054,105.338 U44_L2.6@127.404,105.338 U44_L2.5@126.754,105.338 ; v1(133,100.064) C224_L2.2@133,101.155 ; v1(136.528,100.642) C231_L2.1@136.528,101.184 ; C231_L2.1@136.528,101.434 137.679,101.434 R305_L2.1@137.929,101.184 138.08,101.033 v1(138.879,101.033) 139.328,101.482 139.328,101.742 C236_L2.1@139.541,101.955 ; U37_L2.4@137.034,105.05 137.034,104.673 137.207,104.5 v1(137.733,104.5) ; U39_L2.4@141.56,105.208 U39_L2.5@142.21,105.208 ; C239_L2.1@142.06,103.432 142.183,103.555 142.183,103.676 142.21,103.703 U39_L2.5@142.21,105.208 ; U39_L2.8@144.16,105.208 U39_L2.7@143.51,105.208 ; C237_L2.2@145,102.096 143.355,102.096 143.214,101.955 143.214,103.791 143.51,104.087 U39_L2.7@143.51,105.208 ; U41_L2.5@146.764,105.208 146.764,103.216 v1(146.979,103.001) 147.194,102.786 C240_L2.2@148.2,102.786 ; C206_L2.1@152.075,103.463 152.096,103.484 152.796,103.484 v1(152.817,103.505) 152.838,103.484 153.545,103.484 C209_L2.1@153.566,103.463 153.587,103.484 154.282,103.484 v1(154.303,103.505) 154.324,103.484 155.063,103.484 C207_L2.1@155.084,103.463 ; U33_L2.2@153.956,100.567 v1(153.956,101.18) ; 155.231,98.792 155.323,98.884 v1(156.381,98.884) ; v1(157.005,100.058) C200_L2.2@157.005,101.108 ; v1(160.18,100.698) C205_L2.1@160.18,101.48 ; v1(160.815,100.702) 160.877,100.702 161.091,100.917 161.403,100.917 R295_L2.1@161.75,101.263 161.98,101.033 v1(162.775,101.033) 162.844,101.033 163.027,101.217 163.027,101.507 C219_L2.1@163.25,101.73 ; U32_L2.4@160.815,105.05 160.815,104.723 160.988,104.55 v1(161.503,104.55) ; U34_L2.4@165.175,105 U34_L2.5@165.825,105 ; U34_L2.8@167.775,105 U34_L2.7@167.125,105 U34_L2.6@166.475,105 U34_L2.5@165.825,105 ; C220_L2.2@168.675,101.833 167.063,101.833 166.916,101.98 166.916,102.774 166.508,103.182 C222_L2.1@165.894,103.182 165.859,103.216 165.859,104.966 U34_L2.5@165.825,105 ; v1(172.803,99.934) 172.803,100.908 C186_L2.2@172.825,100.93 ; v1(177.8,103.338) 177.197,103.338 ; v1(177.8,104.401) 177.304,104.401 177.197,104.508 177.197,103.338 ; C196_L2.1@179.497,101.505 179.485,101.492 178.776,101.492 v1(178.763,101.48) 178.025,101.48 R284_L2.1@177.8,101.255 v1(177.8,102.178) 177.8,102.464 177.651,102.613 177.363,102.613 C191_L2.1@177.238,102.738 177.197,102.78 177.197,103.338 ; U29_L2.4@181.447,104.75 U29_L2.5@181.922,104.75 ; C199_L2.1@182.088,103.13 181.965,103.253 181.965,103.359 181.922,103.402 U29_L2.5@181.922,104.75 ; U29_L2.7@183.222,104.85 U29_L2.7@183.222,104.75 ; C198_L2.2@183.354,101.43 183.222,101.562 U29_L2.7@183.222,104.75 ; C197_L2.2@185,102.204 185,104.021 184.309,104.712 183.881,104.712 183.843,104.75 U29_L2.7@183.222,104.75 ; C243_L3.2@202.073,73.155 202.075,73.153 v1(202.075,72.142) ; v1(205.175,72.842) C248_L3.1@205.175,73.609 ; U43_L3.4@205.883,77.226 205.883,76.675 206.056,76.502 206.683,76.502 v1(206.685,76.5) ; R322_L3.1@206.685,73.38 206.7,73.365 v1(206.7,72.317) ; v1(208.201,73.23) 208.215,73.244 208.215,74.041 C253_L3.1@208.228,74.055 ; U44_L3.4@210.104,77.338 U44_L3.5@210.754,77.338 ; C256_L3.1@210.653,75.432 210.653,76.592 210.754,76.693 U44_L3.5@210.754,77.338 ; C255_L3.2@211.77,73.659 212.155,74.044 v1(212.155,75.14) ; 212.497,77.5 212.497,77.338 ; C254_L3.2@214,75.671 213.835,75.671 212.497,77.009 212.497,77.338 ; v1(217,72.064) C224_L3.2@217,73.155 ; v1(220.528,72.642) C231_L3.1@220.528,73.184 ; C231_L3.1@220.528,73.434 221.679,73.434 R305_L3.1@221.929,73.184 222.08,73.033 v1(222.879,73.033) 223.328,73.482 223.328,73.742 C236_L3.1@223.541,73.955 ; U37_L3.4@221.034,77.05 221.034,76.673 221.207,76.5 v1(221.733,76.5) ; U39_L3.4@225.56,77.208 U39_L3.5@226.21,77.208 ; C239_L3.1@226.06,75.432 226.06,76.413 226.21,76.563 U39_L3.5@226.21,77.208 ; U39_L3.8@228.16,77.208 U39_L3.7@227.51,77.208 ; C237_L3.2@229,74.096 227.355,74.096 227.214,73.955 227.214,75.791 227.51,76.087 U39_L3.7@227.51,77.208 ; U41_L3.5@230.764,77.208 230.764,75.216 v1(230.979,75.001) 231.194,74.786 C240_L3.2@232.2,74.786 ; C206_L3.1@236.075,75.463 236.096,75.484 236.796,75.484 v1(236.817,75.505) 236.838,75.484 237.545,75.484 C209_L3.1@237.566,75.463 237.587,75.484 238.282,75.484 v1(238.303,75.505) 238.324,75.484 239.063,75.484 C207_L3.1@239.084,75.463 ; U33_L3.2@237.956,72.567 v1(237.956,73.18) ; 239.231,70.792 239.323,70.884 v1(240.381,70.884) ; v1(241.005,72.058) C200_L3.2@241.005,73.108 ; v1(244.18,72.698) C205_L3.1@244.18,73.48 ; v1(244.815,72.702) 244.877,72.702 245.091,72.917 245.403,72.917 R295_L3.1@245.75,73.263 245.98,73.033 v1(246.775,73.033) 246.844,73.033 247.027,73.217 247.027,73.507 C219_L3.1@247.25,73.73 ; U32_L3.4@244.815,77.05 244.815,76.723 244.988,76.55 244.988,76.523 v1(245.503,76.523) ; U34_L3.4@249.175,77 U34_L3.5@249.825,77 ; U34_L3.8@251.775,77 U34_L3.7@251.125,77 U34_L3.6@250.475,77 U34_L3.5@249.825,77 ; C220_L3.2@252.675,73.833 251.063,73.833 250.916,73.98 250.916,74.774 250.508,75.182 C222_L3.1@249.894,75.182 249.859,75.216 249.859,76.966 U34_L3.5@249.825,77 ; v1(256.803,71.934) 256.803,72.908 C186_L3.2@256.825,72.93 ; v1(261.8,75.338) 261.197,75.338 ; v1(261.8,76.401) 261.304,76.401 261.197,76.508 261.197,75.338 ; C196_L3.1@263.497,73.505 263.485,73.492 262.776,73.492 v1(262.763,73.48) 262.025,73.48 R284_L3.1@261.8,73.255 v1(261.8,74.178) 261.8,74.464 261.651,74.613 261.363,74.613 C191_L3.1@261.238,74.738 261.197,74.78 261.197,75.338 ; U29_L3.4@265.375,76.9 265.375,76.778 265.453,76.7 265.825,76.7 U29_L3.5@265.965,76.84 ; U29_L3.5@265.922,76.75 U29_L3.5@265.965,76.75 ; U29_L3.5@266.025,76.9 U29_L3.5@265.965,76.84 ; C199_L3.1@266.088,75.13 265.965,75.253 U29_L3.5@265.965,76.75 ; U29_L3.7@267.325,76.9 U29_L3.7@267.325,76.75 ; C198_L3.2@267.354,73.43 267.325,73.459 U29_L3.7@267.325,76.75 ; U29_L3.8@267.872,76.672 267.794,76.75 U29_L3.7@267.325,76.75 ; U29_L3.8@267.872,76.85 267.872,76.79 267.95,76.712 268.309,76.712 269.092,75.929 269.092,74.324 C197_L3.2@269.6,73.816 ; U39_L1.5@58.21,120.208 U39_L1.6@58.86,120.208 U39_L1.7@59.51,120.208 ; U29_L1.5@98.097,119.75 U29_L1.7@99.222,119.75 ; U44_N.5@116.162,11.754 U44_N.6@116.162,12.404 U44_N.7@116.162,13.054 116.162,13.497 ; U39_N.5@116.292,27.21 U39_N.6@116.292,27.86 U39_N.7@116.292,28.51 ; U29_N.5@116.75,67.097 U29_N.6@116.75,67.747 U29_N.7@116.75,68.397 ; U39_L2.5@142.21,105.208 U39_L2.6@142.86,105.208 U39_L2.7@143.51,105.208 ; U29_L2.5@181.922,104.75 U29_L2.7@183.222,104.75 ; U44_L3.5@210.754,77.338 U44_L3.6@211.404,77.338 U44_L3.7@212.054,77.338 212.497,77.338 ; U39_L3.5@226.21,77.208 U39_L3.6@226.86,77.208 U39_L3.7@227.51,77.208 ; U29_L3.5@265.965,76.75 266.025,76.75 U29_L3.7@267.325,76.75 ; U29_L3.5@265.965,76.75 U29_L3.5@265.965,76.84
  Top Layer w0.3: U2.9@94.6,246.2 v1(95.3,246.2) ; C34.2@97,243.4 v1(97,242.4) 97,241.7 R105.1@97.2,241.5 ; C30.2@98.8,238 C30.2@98.825,238 ; C78.2@99.2,247.3 v1(100.6,247.3) ; v1@99.43,238.605 v1(99.459,238.605) ; C78.2@99.7,246.5 v1(100.6,246.5) ; C79.2@100.5,243 C79.2@100.6,242.9 ; v1(101.4,241.9) C79.2@101.4,242.9 ; v1(103.9,247.6) C74.2@104.8,247.6 ; C40.2@104.5,230.4 C40.2@104.6,230.5 ; C74.2@104.9,247.6 105.206,247.906 105.206,248.306 105.715,248.815 105.715,249.4 105.915,249.6 U9.5@106,249.6 ; C70.1@110.4,246.2 v1(111.1,246.2) C71.2@112.1,246.2 ; v1(116.1,246.5) C67.2@116.1,247.5 116.3,247.7 116.3,248.3 116.6,248.6 117.024,248.6 117.2,248.776 U8.5@117.2,249.5 ; C63.1@121.3,246 v1(122.1,246) C64.2@123.1,246 ; v1(130,246.7) 130,247.4 C60.2@130.1,247.5 ; C60.2@130.113,247.587 130.45,247.925 130.45,248.45 131.022,249.022 131.022,250.072 U7.5@131.1,250.15 ; C56.1@135.3,246.3 135.321,246.321 v1(136.385,246.321) 137.079,246.321 C57.2@137.1,246.3 ; v1(188.8,203.3) 188.813,203.288 188.813,202.387 U5.9@188.9,202.3 ; R121.1@189.9,206.4 v1(189.9,207.3) ; C46.2@191.7,206.5 191.8,206.6 v1(191.8,207.3) ; C42.2@197.1,206 v1(197.1,207.1) ; Q1.7@289,206 289.8,206 C28.2@289.8,204 R97.1@289.8,202 ; Q1.4@289.88,206 C27.2@291.8,206
  Top Layer w0.35: U3.11@275.6,47.25 276.65,47.25 v1(276.7,47.2)
  Top Layer w0.4: C81.2@80.275,107.25 80.275,107.275 80.55,107.55 80.691,107.55 80.831,107.69 81.062,107.69 v1(81.083,107.711) ; C30.2@98.825,238 v1@99.43,238.605 ; C36.2@113.026,228.074 v1(113.733,228.074) ; R82.1@181.5,43.5 181.6,43.6 v1(181.6,44.5) R81.1@181.6,45.5 ; C52.2@188,51.1 v1(188.8,51.1) ; C230_N.1@192.3,53 v1(192.3,54.1) ; C15.1@197.4,38.1 197.5,38 C15.1@197.5,37.9 v1(197.5,37) 197.54,36.96 197.54,35.94 C16.2@197.5,35.9 ; v1(198.5,57) C161.1@199.1,57 ; v1(199.1,58.6) 199.06,58.64 199.06,59.46 C160.1@199.1,59.5 ; v1(199.1,61.1) C159.1@199.1,61.8 ; J12.111@201.3,46 201.4,45.9 v1(201.4,44.2) ; v1(206.9,28.6) C123.2@207.7,28.6 ; v1(207,44.2) 206.975,44.225 206.975,45.775 J12.97@207,45.8 ; v1(207.4,59.1) C117.2@208.2,59.1 R186.1@208.2,58.1 ; v1(207.7,24.3) C124.2@207.7,25.1 R193.1@207.7,26 ; C123.2@207.7,28.7 R192.1@207.7,29.6 ; C116.2@208.2,61.2 R185.1@208.2,62.2 ; R185.1@208.2,62.3 v1(208.2,63) ; v1(209.6,64.7) 209.604,64.704 210.496,64.704 R184.1@210.5,64.7 ; C115.2@210.487,63.613 C115.2@210.5,63.6 ; R184.1@210.5,64.6 210.5,63.723 C115.2@210.548,63.675 ; C45.2@211.4,56.4 211.4,57.343 211.5,57.443 v1(211.5,57.5) U16.7@211.5,58.2 ; v1(212.6,44.2) 212.575,44.225 212.575,45.775 J12.83@212.6,45.8 ; C114.2@212.9,23.7 212.991,23.791 213.691,23.791 v1(213.7,23.8) R189.1@214.4,23.8 C120.2@214.4,22.7 ; v1(213.6,64.1) C113.2@214.6,64.1 C113.2@214.8,64.1 ; C39.2@214.7,53.4 v1(214.7,54.2) ; v1(215.7,29.3) 215.757,29.3 215.799,29.343 216.857,29.343 U17.7@216.866,29.352 ; v1(215.7,55) C33.2@216.5,55 ; v1(219.7,44.2) J12.65@219.7,45.8 ; v1(220.7,23.854) 220.708,23.862 220.708,24.361 R190.1@220.716,24.369 220.708,24.377 220.708,25.392 C121.2@220.7,25.4 ; R187.1@220.7,57.85 221.55,57.85 v1@221.6,57.9 ; C118.2@220.7,58.85 220.725,58.825 221.475,58.825 v1(221.5,58.8) ; C122.2@220.8,29.2 220.75,29.2 220.7,29.15 R191.1@220.7,28.2 220.75,28.2 221.16,27.79 221.16,27.64 v1(221.2,27.6) ; v1(222.3,59.4) R171.1@223.1,59.4 C110.2@223.1,58.15 ; v1(222.543,63.214) 222.557,63.2 R170.1@223,63.2 ; v1(222.845,25.401) 222.874,25.401 223.123,25.65 223.25,25.65 C130.2@223.3,25.7 ; C109.2@223.1,61.9 R170.1@223.1,63.15 ; C129.2@223.25,28.9 223.3,28.9 223.35,28.95 223.35,29.393 223.4,29.443 v1(223.4,29.5) ; C130.2@223.294,25.906 R203.1@223.294,26.83 ; v1@223.45,29.5 R202.1@223.45,30.15 R202.1@223.5,30.2 ; v1(225.9,65.354) 225.921,65.333 226.467,65.333 C108.2@226.6,65.2 ; C108.2@226.7,65.2 R169.1@228,65.2 ; v1(226.9,57.7) 226.911,57.711 226.911,58.479 226.932,58.5 U15.7@227,58.5 ; C125.2@228.3,25.1 v1(229.3,25.1) v1@229.357,25.1 ; v1(229.6,65.354) 229.621,65.333 229.842,65.333 230.3,64.875 230.3,64.7 C107.2@230.5,64.5 ; v1(230.2,44.1) 230.175,44.125 230.175,45.875 J12.47@230.2,45.9 ; R199.1@230.683,24.472 229.985,24.472 v1@229.357,25.1 ; C126.2@230.8,25.5 229.757,25.5 v1@229.357,25.1 ; J12.46@231,42 230.975,42.025 230.975,43.175 v1(231,43.2) ; J12.38@234.2,42.1 234.175,42.125 234.175,43.175 v1(234.2,43.2) ; v1(235,44.1) 234.975,44.125 234.975,45.275 J12.35@235,45.3 ; R200.1@235.8,27.3 235.9,27.2 236.4,27.2 v1(236.8,26.8) 236.3,26.3 236.21,26.3 C127.2@235.9,26.3 ; C128.2@235.9,30.7 235.95,30.65 236,30.65 236.66,29.99 236.66,29.54 v1(236.7,29.5) R201.1@236.1,29.5 ; R172.1@236.6,57.9 236.6,59.1 236.625,59.125 237.475,59.125 v1(237.5,59.1) ; C112.2@236.6,61.65 R173.1@236.6,63 ; v1(237.4,44.1) 237.375,44.125 237.375,45.375 J12.29@237.4,45.4 ; C66.1@238.4,58 v1(239,58) ; C96.2@239.9,58 v1(240.7,58) ; J12.22@240.5,41.8 240.6,41.9 v1(240.6,43.2) ; v1(241.4,44.1) 241.375,44.125 241.375,45.475 J12.19@241.4,45.5 ; C50.1@242.2,58 v1(242.9,58) ; J12.16@243,42 v1(243,43.2) ; R23.2@244,55 244.1,55.1 v1(244.1,56) ; J12.10@245.4,42 245.375,42.025 245.375,43.175 v1(245.4,43.2) ; C31.1@246,55.1 v1(246.9,55.1) 247.7,55.1 C43.1@247.8,55 ; v1(246.1,44.1) J12.7@246.1,45.7 ; U23.10@281.99,31.76 v1@281.99,33.29 ; U23.6@287.06,32.5 v1@287.6,33.04 ; U23.4@289.55,31.8 v1@289.55,33.15
  Top Layer w0.45: U11.9@83.529,102.904 v1(84.104,102.904)
  Top Layer w0.5: U2.9@93.875,246.175 U2.9@94.4,246.175 ; U4.9@103.034,225.875 103.071,225.911 v1(103.071,227.211) v1(103.071,227.211) 103.072,227.492 104.055,228.475 104.475,228.475 104.6,228.6 C40.2@104.6,230.5 ; C230_L3.1@197.2,52 v1(198.2,52) C230_L2.1@199.3,52 ; C230_L1.1@197.247,55.353 197.3,55.3 197.6,55.3 197.998,54.902 198.298,54.902 198.302,54.898 198.705,54.898 199,54.603 199,54.3 C162.1@199.1,54.2 ; v1(260.798,62.593) 260.799,62.594 261.694,62.594 C82.2@261.7,62.6 ; v1(267.189,44.407) 267.19,44.408 267.19,44.99 C47.1@267.4,45.2 ; C5.2@280.3,42.5 v1(281,42.5) ; C147.2@284.786,36.014 285.024,36.014 285.135,36.125 285.135,36.595 285.172,36.631 v1(285.172,36.634) 285.173,36.635 285.173,38.081 C6.2@285.4,38.308 ; C148.2@285.2,34.6 v1(285.2,35.15) C147.2@285.2,35.6 ; v1(289.152,36.347) C152.2@289.6,35.9 ; C27.2@291.9,206 292,206.1 293.3,206.1 295,207.8 C26.2@295,212.6
  Top Layer w0.7: C80.1@78.375,107.25 C81.2@80.275,107.25
  other v1: 205,4.9 205,5.8 210.8,9 212.3,9 235.6,9.2 237.1,9.2 210.8,10.4 212.3,10.4 235.6,10.6 237.1,10.6 117.541,12.406 118.318,12.406 117.541,13.155 117.541,13.834 118.36,13.834 151.5,15.2 146.35,16.127 149.05,16.276 152.4,16.4 149.05,17.376 156.8,24.2 160.6,24.4 163.3,24.5 134.2,26 135.6,26 137,26 138.4,26 139.8,26 141.2,26 142.6,26 144,26 134.2,27.5 135.6,27.5 137,27.5 138.4,27.5 139.8,27.5 141.2,27.5 142.6,27.5 144,27.5 117.5,27.8 117.8,29.1 186,36.9 187.5,36.9 132.2,38 133.7,38 186,38.3 187.5,38.3 132.2,39.4 133.7,39.4 117.75,52.5 118.5,52.5 117.75,53.25 118.5,53.3 140.6,53.8 142.1,53.8 295,53.8 296.5,53.8 117.718,54 118.499,54 198.3,54.9 140.6,55.2 142.1,55.2 295,55.2 296.5,55.2 295,56.6 296.5,56.6 221.5,57.9 295,58 296.5,58 295,59.4 296.5,59.4 295,60.8 296.5,60.8 276.5,61 278,61 295,62.2 296.5,62.2 236.588,62.296 276.5,62.4 278,62.4 295,63.6 296.5,63.6 295,65 296.5,65 295,66.4 296.5,66.4 295,67.8 296.5,67.8 295,69.2 296.5,69.2 295,70.6 296.5,70.6 295,72 296.5,72 295,73.4 296.5,73.4 295,74.8 296.5,74.8 251.063,75.001 227.9,75.5 267.742,75.556 266.538,75.605 226.7,76 211.2,76.1 252.4,76.1 268.774,76.895 183.2,89.8 183.2,91.2 294.6,92.6 296.1,92.6 294.6,94 296.1,94 280,95.2 281.5,95.2 294.5,95.7 296,95.7 280,96.6 281.5,96.6 294.5,97.1 296,97.1 280,98 281.5,98 294.5,98.5 296,98.5 280,99.4 281.5,99.4 294.5,99.9 296,99.9 280,100.8 281.5,100.8 294.5,101.3 296,101.3 280,102.2 281.5,102.2 294.5,102.7 296,102.7 92.6,102.9 168.7,103.1 185.5,103.1 182.8,103.5 183.8,103.5 167.1,103.6 280,103.6 281.5,103.6 144.9,103.7 142.7,103.8 94.1,104 294.5,104.1 296,104.1 280,105 281.5,105 94.15,105.1 294.5,105.5 296,105.5 280,106.4 281.5,106.4 294.5,106.9 296,106.9 280,107.8 281.5,107.8 294.5,108.3 296,108.3 280,109.2 281.5,109.2 294.5,109.7 296,109.7 280,110.6 281.5,110.6 294.5,111.1 296,111.1 280,112 281.5,112 294.5,112.5 296,112.5 280,113.4 281.5,113.4 294.5,113.9 296,113.9 280,114.8 281.5,114.8 294.5,115.3 296,115.3 280,116.2 281.5,116.2 294.5,116.7 296,116.7 280,117.6 281.5,117.6 83.063,118.001 294.5,118.1 296,118.1 58.7,118.3 98.7,118.5 100.3,118.5 84.3,118.6 60.1,118.9 280,119 281.5,119 43.5,119.1 44.7,119.1 294.5,119.5 296,119.5 280,120.4 281.5,120.4 294.5,120.9 296,120.9 280,121.8 281.5,121.8 294.5,122.3 296,122.3 280,123.2 281.5,123.2 294.5,123.7 296,123.7 280,124.6 281.5,124.6 294.5,125.1 296,125.1 280,126 281.5,126 294.5,126.5 296,126.5 280,127.4 281.5,127.4 294.5,127.9 296,127.9 280,128.8 281.5,128.8 294.5,129.3 296,129.3 280,130.2 281.5,130.2 294.5,130.7 296,130.7 280,131.6 281.5,131.6 280,133 281.5,133 280,134.4 281.5,134.4 280,135.8 281.5,135.8 280,137.2 281.5,137.2 280,138.6 281.5,138.6 294.7,169.3 296.2,169.3 294.7,170.7 296.2,170.7 294.7,172.1 296.2,172.1 294.7,173.5 296.2,173.5 294.7,174.9 296.2,174.9 294.7,176.3 296.2,176.3 294.7,177.7 296.2,177.7 294.7,179.1 296.2,179.1 294.7,180.5 296.2,180.5 294.7,181.9 296.2,181.9 294.7,183.3 296.2,183.3 294.7,184.7 296.2,184.7 294.7,186.1 296.2,186.1 294.7,187.5 296.2,187.5 294.7,188.9 296.2,188.9 294.7,190.3 296.2,190.3 294.7,191.7 296.2,191.7 294.7,193.1 296.2,193.1 294.7,194.5 296.2,194.5 294.7,195.9 296.2,195.9 294.7,197.3 296.2,197.3 294.7,198.7 296.2,198.7 294.7,200.1 296.2,200.1 294.7,201.5 296.2,201.5 289.446,202.1 294.7,202.9 296.2,202.9 289.446,204 294.7,204.3 296.2,204.3 151.6,233.8 153.1,233.8 151.6,235.2 153.1,235.2 99.1,249.7 100.1,249.7 101.1,249.7
GND_HVN: C94.2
